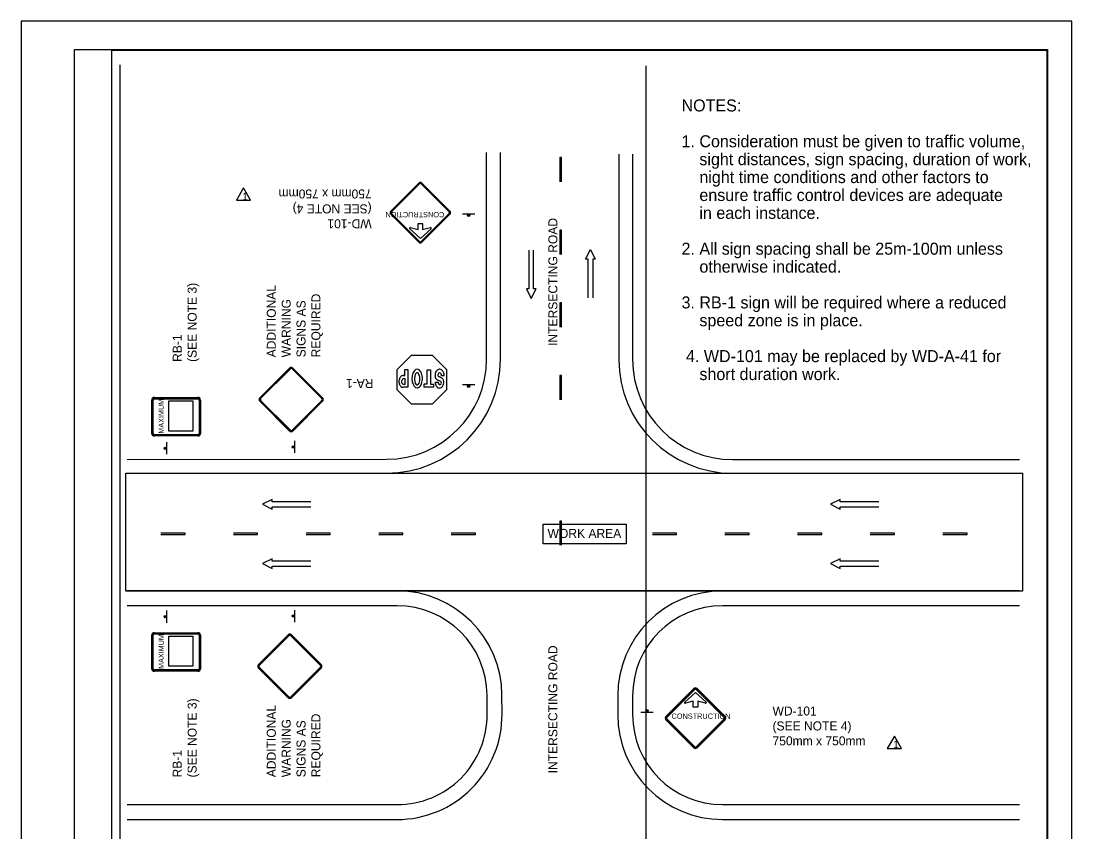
# Model space of a CAD drawing. Extents: x 1373 to 1583, y 130 to 399.
# Drawn here: x 1373.1 to 1583.1, y 237.1 to 399 of the extents above; entities that cross this region are included whole.
import ezdxf

# ---------------------------------------------------------------- set-up
doc = ezdxf.new("R2010")
doc.units = 0
for name, color, linetype in [('Level 1', 7, 'Continuous'), ('Level 10', 7, 'Continuous'), ('Level 17', 7, 'Continuous'), ('Level 18', 7, 'Continuous'), ('Level 2', 7, 'Continuous'), ('Level 60', 7, 'Continuous')]:
    doc.layers.add(name, color=color, linetype=linetype)

msp = doc.modelspace()

# ---------------------------------------------------------------- linework, layer by layer
at = {"layer": 'Level 10'}
for p, q in [((1392.81, 390.25), (1392.81, 138.3)), ((1497.88, 390.01), (1497.88, 138.3)), ((1466.08, 331.48), (1466.08, 372.74)), ((1468.86, 331.48), (1468.86, 372.74)), ((1492.53, 372.39), (1492.53, 331.41)), ((1495.25, 372.39), (1495.25, 331.41)), ((1474.51, 353.24), (1474.51, 345.5)), ((1475.48, 345.5), (1475.48, 353.24)), ((1485.87, 351.43), (1486.84, 353.37)), ((1486.84, 353.37), (1487.8, 351.43)), ((1486.35, 351.43), (1485.87, 351.43)), ((1486.35, 343.69), (1486.35, 351.43)), ((1487.8, 351.43), (1487.32, 351.43)), ((1487.32, 351.43), (1487.32, 343.69)), ((1474.03, 345.5), (1475, 343.56)), ((1474.51, 345.5), (1474.03, 345.5)), ((1475, 343.56), (1475.96, 345.5)), ((1475.96, 345.5), (1475.48, 345.5)), ((1449.75, 328.2), (1449.37, 328.2)), ((1449.39, 328.19), (1449.75, 328.2)), ((1449.75, 328.2), (1449.75, 329.43)), ((1449.75, 329.43), (1450.35, 329.43)), ((1450.35, 329.43), (1450.35, 325.84)), ((1454.23, 329.32), (1454.85, 329.32)), ((1454.23, 326.51), (1454.23, 329.32)), ((1454.85, 329.32), (1454.85, 326.5)), ((1457.63, 328.16), (1457.07, 328.16)), ((1457.45, 328.87), (1457.45, 328.87)), ((1450.35, 325.84), (1449.34, 325.84)), ((1449.43, 326.48), (1449.82, 326.48)), ((1449.43, 326.48), (1449.82, 326.48)), ((1449.82, 327.53), (1449.44, 327.53)), ((1449.82, 327.53), (1449.44, 327.53)), ((1449.82, 326.48), (1449.82, 327.53)), ((1449.82, 326.48), (1449.82, 327.53)), ((1452.25, 325.71), (1452.24, 325.71)), ((1452.28, 326.32), (1452.25, 326.32)), ((1453.6, 325.87), (1453.6, 326.51)), ((1453.6, 326.51), (1454.23, 326.51)), ((1455.51, 325.87), (1453.6, 325.87)), ((1454.85, 326.5), (1455.51, 326.5)), ((1455.51, 326.5), (1455.51, 325.87)), ((1455.81, 326.87), (1456.42, 326.87)), ((1394.25, 311.41), (1446.1, 311.48)), ((1515.25, 311.41), (1572.59, 311.41)), ((1394.25, 308.63), (1446.11, 308.7)), ((1515.25, 308.68), (1572.59, 308.68)), ((1423.23, 303.45), (1421.29, 302.49)), ((1421.29, 302.49), (1423.23, 301.52)), ((1423.23, 302.97), (1423.23, 303.45)), ((1430.97, 302.97), (1423.23, 302.97)), ((1536.75, 303.45), (1534.81, 302.49)), ((1534.81, 302.49), (1536.75, 301.52)), ((1536.75, 302.97), (1536.75, 303.45)), ((1544.49, 302.97), (1536.75, 302.97)), ((1423.23, 301.52), (1423.23, 302)), ((1423.23, 302), (1430.97, 302)), ((1536.75, 301.52), (1536.75, 302)), ((1536.75, 302), (1544.49, 302)), ((1423.23, 291.62), (1421.29, 290.65)), ((1421.29, 290.65), (1423.23, 289.68)), ((1423.23, 291.13), (1423.23, 291.62)), ((1430.97, 291.13), (1423.23, 291.13)), ((1423.23, 289.68), (1423.23, 290.16)), ((1423.23, 290.16), (1430.97, 290.16)), ((1536.75, 291.62), (1534.81, 290.65)), ((1534.81, 290.65), (1536.75, 289.68)), ((1536.75, 291.13), (1536.75, 291.62)), ((1544.49, 291.13), (1536.75, 291.13)), ((1536.75, 289.68), (1536.75, 290.16)), ((1536.75, 290.16), (1544.49, 290.16)), ((1572.59, 285.2), (1394.25, 285.2)), ((1448.19, 285.2), (1394.25, 285.2)), ((1572.59, 285.2), (1513.25, 285.2)), ((1448.19, 282.23), (1394.25, 282.23)), ((1572.59, 282.23), (1513.25, 282.23)), ((1466.21, 260.63), (1466.19, 264.35)), ((1469.17, 260.65), (1469.15, 264.36)), ((1492.29, 264.23), (1492.29, 260.52)), ((1495.25, 264.23), (1495.25, 260.52)), ((1394.25, 242.52), (1448.21, 242.52)), ((1513.25, 242.52), (1572.59, 242.52)), ((1394.25, 239.56), (1448.21, 239.56)), ((1513.25, 239.56), (1572.59, 239.56))]:
    msp.add_line(p, q, dxfattribs=at)
for points in [[(1448.24, 329.4), (1451.1, 332.27), (1455.18, 332.27), (1458.05, 329.4), (1458.05, 325.32), (1455.18, 322.45), (1451.1, 322.45), (1448.24, 325.32)], [(1573.19, 308.68), (1573.19, 285.11), (1394.01, 285.11), (1394.01, 308.68)], [(1477.39, 298.55), (1493.95, 298.55), (1493.95, 294.58), (1477.39, 294.58)]]:
    msp.add_lwpolyline(points, close=True, dxfattribs=at)
for centre, radius, start, end in [((1446.08, 331.48), 20, 270.0814, 0), ((1446.08, 331.48), 22.78, 270.0814, 0), ((1515.25, 331.41), 22.73, 180, 270), ((1515.25, 331.41), 20, 180, 270), ((1450.55, 326.91), 1.98, 158.3153, 168.6699), ((1449.61, 327.29), 0.968, 138.2922, 158.6031), ((1449.61, 327.29), 0.968, 138.2922, 158.6031), ((1449.35, 327.57), 0.597, 115.3838, 142.6188), ((1449.53, 327.34), 0.882, 106.602, 119.8091), ((1449.35, 327.99), 0.207, 79.7909, 113.5419), ((1457.94, 328.25), 2.16, 171.247, 183.9864), ((1457.3, 328.25), 1.53, 185.9097, 201.9865), ((1457.43, 328.1), 1.7, 145.5092, 163.2894), ((1454.04, 325.89), 2.57, 39.479, 43.426), ((1456.83, 328.5), 0.977, 113.1413, 144.9906), ((1456.75, 328.28), 0.399, 172.5761, 210.4776), ((1456.87, 328.33), 0.516, 146.253, 178.7323), ((1456.77, 328.33), 0.435, 214.2083, 254.1552), ((1456.71, 328.33), 0.388, 95.4374, 134.0626), ((1456.69, 328.83), 0.612, 52.0536, 112.7397), ((1454.16, 321.47), 6.9, 64.4624, 68.8312), ((1456.68, 328.29), 0.419, 50.6966, 91.4573), ((1456.62, 328.33), 0.43, 6.8728, 42.7449), ((1456.21, 328.17), 0.856, 359.0172, 13.5172), ((1456.27, 328.24), 1.34, 28.4154, 53.6553), ((1456.6, 326.91), 0.952, 20.4481, 55.1107), ((1455.75, 328.08), 1.88, 2.3841, 24.9519), ((1450.1, 327.03), 1.52, 169.7521, 182.7916), ((1450.1, 327.03), 1.52, 169.7521, 182.7916), ((1450.47, 327.06), 1.89, 183.3903, 195.6597), ((1449.59, 326.78), 0.972, 193.0674, 213.762), ((1449.58, 326.69), 0.915, 209.2241, 228.5308), ((1449.58, 326.69), 0.915, 209.2241, 228.5308), ((1449.39, 326.43), 0.596, 224.8528, 265.0441), ((1449.68, 327), 0.585, 170.3417, 195.2342), ((1449.68, 327), 0.585, 170.3417, 195.2342), ((1449.62, 327.07), 0.522, 146.5086, 177.0313), ((1449.62, 327.07), 0.522, 146.5086, 177.0313), ((1449.66, 326.93), 0.55, 188.6031, 214.217), ((1449.66, 326.93), 0.55, 188.6031, 214.217), ((1449.52, 327.13), 0.406, 101.9191, 145.7868), ((1449.52, 327.13), 0.406, 101.9191, 145.7868), ((1449.49, 326.82), 0.354, 215.1198, 259.3117), ((1449.49, 326.82), 0.354, 215.1198, 259.3117), ((1457.36, 326.9), 1.55, 180.6952, 197.1452), ((1456.97, 326.72), 1.12, 194.564, 229.0063), ((1457.04, 328.58), 1.47, 226.2465, 247.9263), ((1456.69, 326.36), 0.665, 226.1369, 301.3987), ((1456.91, 326.8), 0.506, 170.4412, 219.3244), ((1455.8, 325.23), 2.1, 57.9816, 70.979), ((1456.75, 326.74), 0.346, 227.3017, 289.0119), ((1456.72, 326.71), 0.331, 293.8064, 352.2407), ((1456.76, 326.76), 0.302, 344.131, 58.1476), ((1456.44, 326.7), 1.09, 303.3662, 335.6734), ((1456.02, 326.83), 1.52, 337.7332, 357.1392), ((1456.21, 326.87), 1.34, 354.8171, 15.9183), ((1448.19, 264.23), 20.97, 0.3535, 90), ((1513.25, 264.23), 20.97, 90, 180), ((1448.19, 264.23), 18, 0.3535, 90), ((1513.25, 264.23), 18, 90, 180), ((1448.21, 260.52), 20.97, 270, 0.3535), ((1448.21, 260.52), 18, 270, 0.3535), ((1513.25, 260.52), 20.97, 180, 270), ((1513.25, 260.52), 18, 180, 270)]:
    msp.add_arc(centre, radius, start, end, dxfattribs=at)
for centre, major_axis, ratio, start_param, end_param in [((1452.22, 327.58), (0.01, 1.87), 0.558644, 0.656861, 3.168126), ((1452.22, 327.58), (0.01, 1.87), 0.558644, 4.129576, 6.939747), ((1452.22, 327.54), (-0.01, 1.22), 0.432619, 0.881967, 3.190734), ((1452.22, 327.54), (-0.01, 1.22), 0.432619, 3.890436, 7.165085), ((1452.22, 327.58), (0.01, 1.87), 0.558644, 3.185857, 4.129398), ((1452.22, 327.54), (-0.01, 1.22), 0.432619, 3.239639, 3.888884)]:
    msp.add_ellipse(centre, major_axis=major_axis, ratio=ratio, start_param=start_param, end_param=end_param, dxfattribs=at)
at = {"layer": 'Level 17'}
for p, q in [((1383.77, 393.31), (1383.77, 393.31)), ((1446.94, 361.03), (1452.54, 366.63)), ((1447.03, 360.94), (1452.63, 366.54)), ((1447.11, 360.86), (1452.71, 366.46)), ((1453.01, 366.46), (1458.61, 360.86)), ((1453.09, 366.54), (1458.69, 360.94)), ((1453.17, 366.63), (1458.77, 361.03)), ((1452.54, 354.8), (1446.94, 360.39)), ((1452.63, 354.88), (1447.03, 360.48)), ((1452.71, 354.96), (1447.11, 360.56)), ((1458.61, 360.56), (1453.01, 354.96)), ((1458.69, 360.48), (1453.09, 354.88)), ((1458.77, 360.39), (1453.17, 354.8)), ((1459.09, 360.71), (1459.09, 360.71)), ((1463.71, 360.44), (1461.29, 360.44)), ((1454.88, 357.74), (1454.88, 357.74)), ((1454.88, 357.74), (1454.88, 357.74)), ((1454.88, 357.74), (1454.88, 357.74)), ((1420.77, 323.75), (1426.69, 329.68)), ((1420.86, 323.67), (1426.78, 329.59)), ((1420.94, 323.58), (1426.87, 329.5)), ((1427.22, 329.5), (1433.14, 323.58)), ((1427.31, 329.59), (1433.23, 323.67)), ((1427.39, 329.68), (1433.32, 323.75)), ((1463.71, 326.34), (1461.29, 326.34)), ((1399.7, 323.83), (1408.4, 323.83)), ((1399.7, 323.7), (1408.4, 323.7)), ((1399.7, 323.57), (1408.4, 323.57)), ((1420.77, 323.75), (1420.77, 323.75)), ((1420.85, 323.67), (1420.86, 323.67)), ((1420.94, 323.58), (1420.94, 323.58)), ((1399.19, 316.64), (1399.19, 323.31)), ((1399.32, 316.64), (1399.32, 323.31)), ((1399.45, 316.64), (1399.45, 323.31)), ((1408.66, 323.31), (1408.66, 316.64)), ((1408.79, 323.31), (1408.79, 316.64)), ((1408.91, 323.31), (1408.91, 316.64)), ((1426.69, 317.12), (1420.77, 323.05)), ((1426.78, 317.21), (1420.85, 323.14)), ((1426.87, 317.3), (1420.94, 323.23)), ((1433.14, 323.23), (1427.22, 317.3)), ((1433.23, 323.14), (1427.31, 317.21)), ((1433.32, 323.05), (1427.39, 317.12)), ((1399.19, 316.64), (1399.19, 316.64)), ((1399.24, 316.52), (1399.24, 316.52)), ((1399.29, 316.41), (1399.29, 316.41)), ((1408.4, 316.38), (1399.7, 316.38)), ((1408.4, 316.25), (1399.7, 316.25)), ((1408.4, 316.13), (1399.7, 316.13)), ((1427.74, 312.73), (1427.74, 315.15)), ((1402.16, 312.47), (1402.16, 314.88)), ((1402.16, 278.85), (1402.16, 281.27)), ((1427.74, 278.94), (1427.74, 281.36)), ((1399.19, 269.66), (1399.19, 276.33)), ((1399.32, 269.66), (1399.32, 276.33)), ((1399.45, 269.66), (1399.45, 276.33)), ((1399.7, 276.85), (1408.4, 276.85)), ((1399.7, 276.72), (1408.4, 276.72)), ((1399.7, 276.59), (1408.4, 276.59)), ((1408.66, 276.33), (1408.66, 269.66)), ((1408.79, 276.33), (1408.79, 269.66)), ((1408.91, 276.33), (1408.91, 269.66)), ((1420.5, 270.5), (1426.42, 276.42)), ((1420.58, 270.41), (1426.51, 276.33)), ((1420.67, 270.32), (1426.6, 276.24)), ((1426.94, 276.24), (1432.87, 270.32)), ((1427.03, 276.33), (1432.96, 270.41)), ((1427.12, 276.42), (1433.05, 270.5)), ((1399.19, 269.66), (1399.19, 269.66)), ((1399.24, 269.55), (1399.24, 269.55)), ((1399.29, 269.43), (1399.29, 269.43)), ((1408.4, 269.41), (1399.7, 269.41)), ((1408.4, 269.28), (1399.7, 269.28)), ((1408.4, 269.15), (1399.7, 269.15)), ((1420.49, 270.49), (1420.5, 270.5)), ((1426.42, 263.86), (1420.5, 269.8)), ((1420.58, 270.41), (1420.58, 270.41)), ((1426.51, 263.95), (1420.58, 269.88)), ((1420.67, 270.32), (1420.67, 270.32)), ((1426.6, 264.04), (1420.67, 269.97)), ((1432.87, 269.97), (1426.94, 264.04)), ((1432.96, 269.88), (1427.03, 263.95)), ((1433.05, 269.8), (1427.12, 263.86)), ((1501.91, 260.11), (1507.51, 265.71)), ((1501.99, 260.02), (1507.59, 265.62)), ((1502.08, 259.94), (1507.68, 265.54)), ((1507.97, 265.54), (1513.58, 259.94)), ((1508.06, 265.62), (1513.66, 260.02)), ((1508.14, 265.71), (1513.74, 260.11)), ((1505.81, 262.77), (1505.81, 262.77)), ((1505.81, 262.77), (1505.81, 262.77)), ((1505.81, 262.77), (1505.81, 262.77)), ((1496.93, 261.01), (1499.35, 261.01)), ((1501.59, 259.79), (1501.59, 259.79)), ((1507.51, 253.88), (1501.91, 259.48)), ((1507.59, 253.96), (1501.99, 259.56)), ((1507.68, 254.04), (1502.08, 259.64)), ((1513.58, 259.64), (1507.97, 254.04)), ((1513.66, 259.56), (1508.06, 253.96)), ((1513.74, 259.48), (1508.14, 253.88))]:
    msp.add_line(p, q, dxfattribs=at)
for points in [[(1455, 357.51), (1452.86, 355.56), (1450.72, 357.51)], [(1455, 357.51), (1452.86, 355.56), (1450.72, 357.51)], [(1455, 357.51), (1452.86, 355.56), (1450.72, 357.51)], [(1450.84, 357.74), (1452.42, 357.33), (1452.42, 358.56), (1453.31, 358.56), (1453.31, 357.33), (1454.88, 357.74)], [(1450.84, 357.74), (1452.42, 357.33), (1452.42, 358.56), (1453.31, 358.56), (1453.31, 357.33), (1454.88, 357.74)], [(1450.84, 357.74), (1452.42, 357.33), (1452.42, 358.56), (1453.31, 358.56), (1453.31, 357.33), (1454.88, 357.74)], [(1505.68, 263), (1507.82, 264.94), (1509.97, 263)], [(1505.68, 263), (1507.82, 264.94), (1509.97, 263)], [(1505.68, 263), (1507.82, 264.94), (1509.97, 263)], [(1509.84, 262.77), (1508.27, 263.17), (1508.27, 261.95), (1507.38, 261.95), (1507.38, 263.17), (1505.81, 262.77)], [(1509.84, 262.77), (1508.27, 263.17), (1508.27, 261.95), (1507.38, 261.95), (1507.38, 263.17), (1505.81, 262.77)], [(1509.84, 262.77), (1508.27, 263.17), (1508.27, 261.95), (1507.38, 261.95), (1507.38, 263.17), (1505.81, 262.77)]]:
    msp.add_lwpolyline(points, dxfattribs=at)
for points in [[(1402.58, 323.13), (1407.39, 323.13), (1407.39, 317.11), (1402.58, 317.11)], [(1402.58, 276.15), (1407.39, 276.15), (1407.39, 270.14), (1402.58, 270.14)]]:
    msp.add_lwpolyline(points, close=True, dxfattribs=at)
for centre, radius in [((1462.5, 360.17), 0.242), ((1462.5, 360.17), 0.121), ((1462.5, 326.07), 0.242), ((1462.5, 326.07), 0.121), ((1401.89, 313.68), 0.242), ((1401.89, 313.68), 0.121), ((1427.47, 313.94), 0.242), ((1427.47, 313.94), 0.121), ((1401.89, 280.06), 0.242), ((1401.89, 280.06), 0.121), ((1427.47, 280.16), 0.242), ((1427.47, 280.16), 0.121), ((1498.15, 261.28), 0.242), ((1498.15, 261.28), 0.121)]:
    msp.add_circle(centre, radius, dxfattribs=at)
for centre, radius, start, end in [((1452.86, 366.31), 0.447, 45, 135), ((1452.86, 366.31), 0.329, 45, 135), ((1452.86, 366.31), 0.212, 45, 135), ((1447.26, 360.71), 0.447, 135, 225), ((1447.26, 360.71), 0.329, 135, 225), ((1447.26, 360.71), 0.212, 135, 225), ((1458.46, 360.71), 0.212, 315, 45), ((1458.46, 360.71), 0.329, 315, 45), ((1458.46, 360.71), 0.447, 315, 45), ((1450.81, 357.61), 0.134, 75.5925, 227.6952), ((1450.81, 357.61), 0.134, 75.5925, 227.6952), ((1450.81, 357.61), 0.134, 75.5925, 227.6952), ((1454.91, 357.61), 0.134, 312.3048, 104.4075), ((1454.91, 357.61), 0.134, 312.3048, 104.4075), ((1454.91, 357.61), 0.134, 312.3048, 104.4075), ((1452.86, 355.11), 0.212, 225, 315), ((1452.86, 355.11), 0.447, 225, 315), ((1452.86, 355.11), 0.329, 225, 315), ((1427.04, 329.33), 0.496, 45, 135), ((1427.04, 329.33), 0.371, 45, 135), ((1427.04, 329.33), 0.246, 45, 135), ((1399.7, 323.31), 0.515, 90, 180), ((1399.7, 323.31), 0.386, 90, 180), ((1399.7, 323.31), 0.258, 90, 180), ((1408.4, 323.31), 0.515, 0, 90), ((1408.4, 323.31), 0.386, 0, 90), ((1408.4, 323.31), 0.258, 0, 90), ((1421.12, 323.4), 0.496, 135, 225), ((1421.12, 323.4), 0.371, 135, 225), ((1421.12, 323.4), 0.246, 135, 225), ((1432.97, 323.4), 0.246, 315, 45), ((1432.97, 323.4), 0.371, 315, 45), ((1432.97, 323.4), 0.496, 315, 45), ((1427.04, 317.48), 0.496, 225, 315), ((1427.04, 317.48), 0.371, 225, 315), ((1427.04, 317.48), 0.246, 225, 315), ((1399.7, 316.64), 0.515, 180, 270), ((1399.7, 316.64), 0.386, 180, 270), ((1399.7, 316.64), 0.258, 180, 270), ((1408.4, 316.64), 0.515, 270, 0), ((1408.4, 316.64), 0.386, 270, 0), ((1408.4, 316.64), 0.258, 270, 0), ((1399.7, 276.33), 0.515, 90, 180), ((1399.7, 276.33), 0.386, 90, 180), ((1399.7, 276.33), 0.258, 90, 180), ((1408.4, 276.33), 0.515, 0, 90), ((1408.4, 276.33), 0.386, 0, 90), ((1408.4, 276.33), 0.258, 0, 90), ((1426.77, 276.07), 0.496, 45, 135), ((1426.77, 276.07), 0.371, 45, 135), ((1426.77, 276.07), 0.246, 45, 135), ((1399.7, 269.66), 0.515, 180, 270), ((1399.7, 269.66), 0.386, 180, 270), ((1399.7, 269.66), 0.258, 180, 270), ((1408.4, 269.66), 0.515, 270, 0), ((1408.4, 269.66), 0.386, 270, 0), ((1408.4, 269.66), 0.258, 270, 0), ((1420.84, 270.14), 0.496, 135, 225), ((1420.84, 270.14), 0.371, 135, 225), ((1420.84, 270.14), 0.246, 135, 225), ((1432.7, 270.14), 0.246, 315, 45), ((1432.7, 270.14), 0.371, 315, 45), ((1432.7, 270.14), 0.496, 315, 45), ((1507.82, 265.39), 0.447, 45, 135), ((1507.82, 265.39), 0.329, 45, 135), ((1507.82, 265.39), 0.212, 45, 135), ((1426.77, 264.22), 0.496, 225, 315), ((1426.77, 264.22), 0.371, 225, 315), ((1426.77, 264.22), 0.246, 225, 315), ((1505.77, 262.9), 0.134, 132.3048, 284.4075), ((1505.77, 262.9), 0.134, 132.3048, 284.4075), ((1505.77, 262.9), 0.134, 132.3048, 284.4075), ((1509.87, 262.9), 0.134, 255.5925, 47.6952), ((1509.87, 262.9), 0.134, 255.5925, 47.6952), ((1509.87, 262.9), 0.134, 255.5925, 47.6952), ((1502.22, 259.79), 0.447, 135, 225), ((1502.22, 259.79), 0.329, 135, 225), ((1502.22, 259.79), 0.212, 135, 225), ((1513.42, 259.79), 0.212, 315, 45), ((1513.42, 259.79), 0.329, 315, 45), ((1513.42, 259.79), 0.447, 315, 45), ((1507.82, 254.19), 0.447, 225, 315), ((1507.82, 254.19), 0.329, 225, 315), ((1507.82, 254.19), 0.212, 225, 315)]:
    msp.add_arc(centre, radius, start, end, dxfattribs=at)
at = {"layer": 'Level 2'}
for p, q in [((1480.75, 371.71), (1480.75, 366.87)), ((1481.04, 371.71), (1480.75, 371.71)), ((1481.04, 366.87), (1481.04, 371.71)), ((1480.75, 357.19), (1480.75, 352.36)), ((1481.04, 357.19), (1480.75, 357.19)), ((1481.04, 352.36), (1481.04, 357.19)), ((1480.75, 342.68), (1480.75, 337.84)), ((1481.04, 342.68), (1480.75, 342.68)), ((1481.04, 337.84), (1481.04, 342.68)), ((1480.75, 328.17), (1480.75, 323.33)), ((1481.04, 328.17), (1480.75, 328.17)), ((1481.04, 323.33), (1481.04, 328.17)), ((1480.75, 299.14), (1480.75, 294.3)), ((1481.04, 299.14), (1480.75, 299.14)), ((1481.04, 294.3), (1481.04, 299.14)), ((1405.83, 296.73), (1400.99, 296.73)), ((1400.99, 296.44), (1405.83, 296.44)), ((1405.83, 296.44), (1405.83, 296.73)), ((1420.34, 296.73), (1415.5, 296.73)), ((1415.5, 296.44), (1420.34, 296.44)), ((1420.34, 296.44), (1420.34, 296.73)), ((1434.85, 296.73), (1430.02, 296.73)), ((1430.02, 296.44), (1434.85, 296.44)), ((1434.85, 296.44), (1434.85, 296.73)), ((1449.37, 296.73), (1444.53, 296.73)), ((1444.53, 296.44), (1449.37, 296.44)), ((1449.37, 296.44), (1449.37, 296.73)), ((1463.88, 296.73), (1459.04, 296.73)), ((1459.04, 296.44), (1463.88, 296.44)), ((1463.88, 296.44), (1463.88, 296.73)), ((1504.05, 296.73), (1499.21, 296.73)), ((1499.21, 296.44), (1504.05, 296.44)), ((1504.05, 296.44), (1504.05, 296.73)), ((1518.56, 296.73), (1513.72, 296.73)), ((1513.72, 296.44), (1518.56, 296.44)), ((1518.56, 296.44), (1518.56, 296.73)), ((1533.07, 296.73), (1528.24, 296.73)), ((1528.24, 296.44), (1533.07, 296.44)), ((1533.07, 296.44), (1533.07, 296.73)), ((1547.59, 296.73), (1542.75, 296.73)), ((1542.75, 296.44), (1547.59, 296.44)), ((1547.59, 296.44), (1547.59, 296.73)), ((1562.1, 296.73), (1557.26, 296.73)), ((1557.26, 296.44), (1562.1, 296.44)), ((1562.1, 296.44), (1562.1, 296.73))]:
    msp.add_line(p, q, dxfattribs=at)
at = {"layer": 'Level 60'}
for p, q in [((1583.06, 398.98), (1373.06, 398.98)), ((1373.06, 398.98), (1373.06, 129.98)), ((1583.06, 129.98), (1583.06, 398.98))]:
    msp.add_line(p, q, dxfattribs=at)
for points in [[(1383.77, 393.31), (1578.17, 393.31), (1578.17, 135.56), (1383.77, 135.56)], [(1391.18, 393.17), (1578.06, 393.17), (1578.06, 135.79), (1391.18, 135.79)], [(1417.52, 365.66), (1416.1, 363.19), (1418.94, 363.19)], [(1547.58, 256.22), (1546.16, 253.75), (1549, 253.75)]]:
    msp.add_lwpolyline(points, close=True, dxfattribs=at)

# ---------------------------------------------------------------- texts
at = {"layer": 'Level 1'}
for s, p in [('NOTES:', (1505.04, 380.92)), ('1. Consideration must be given to traffic volume,', (1505.04, 373.77)), ('    sight distances, sign spacing, duration of work,', (1505.04, 370.19)), ('    night time conditions and other factors to ', (1505.04, 366.62)), ('    ensure traffic control devices are adequate ', (1505.04, 363.04)), ('    in each instance.', (1505.04, 359.47)), ('2. All sign spacing shall be 25m-100m unless', (1505.04, 352.32)), ('    otherwise indicated.', (1505.04, 348.74)), ('3. RB-1 sign will be required where a reduced ', (1505.04, 341.59)), ('    speed zone is in place.', (1505.04, 338.02)), (' 4. WD-101 may be replaced by WD-A-41 for ', (1505.04, 330.87)), ('    short duration work.', (1505.04, 327.29))]:
    msp.add_text(s, height=2.4, dxfattribs=at).set_placement(p)
at = {"layer": 'Level 10'}
for s, rotation, p in [('INTERSECTING ROAD', 90, (1480.23, 334.11)), ('WORK AREA', 360, (1478.28, 295.77)), ('INTERSECTING ROAD', 90, (1480.23, 248.77))]:
    msp.add_text(s, height=1.8, rotation=rotation, dxfattribs=at).set_placement(p)
at = {"layer": 'Level 17'}
for s, height, rotation, p in [('750mm x 750mm', 1.8, 180, (1443.12, 365.35)), ('(SEE NOTE 4)', 1.8, 180, (1443.12, 362.37)), ('WD-101', 1.8, 180, (1443.12, 359.4)), ('CONSTRUCTION', 1.0575, 180, (1457.64, 360.85)), ('ADDITIONAL ', 1.7999, 90, (1423.97, 331.83)), ('REQUIRED', 1.8, 90, (1432.88, 331.83)), ('WARNING ', 1.8, 90, (1426.94, 331.83)), ('SIGNS AS ', 1.8, 90, (1429.91, 331.83)), ('RA-1', 1.8, 180, (1443.48, 327.49)), ('MAXIMUM', 1.039, 90, (1401.59, 316.6)), ('MAXIMUM', 1.039, 90, (1401.59, 269.62)), ('ADDITIONAL ', 1.7999, 90, (1423.97, 247.99)), ('REQUIRED', 1.8, 90, (1432.88, 247.99)), ('WARNING ', 1.8, 90, (1426.94, 247.99)), ('SIGNS AS ', 1.8, 90, (1429.91, 247.99))]:
    msp.add_text(s, height=height, rotation=rotation, dxfattribs=at).set_placement(p)
for s, height, p in [('CONSTRUCTION', 1.0575, (1503.05, 259.65)), ('WD-101', 1.8, (1523.22, 260.31)), ('(SEE NOTE 4)', 1.8, (1523.22, 257.33)), ('750mm x 750mm', 1.8, (1523.22, 254.36))]:
    msp.add_text(s, height=height, dxfattribs=at).set_placement(p)
at = {"layer": 'Level 18'}
for s, p in [('(SEE NOTE 3)', (1408.15, 330.92)), ('RB-1', (1405.17, 330.92)), ('(SEE NOTE 3)', (1408.15, 247.95)), ('RB-1', (1405.17, 247.95))]:
    msp.add_text(s, height=1.8, rotation=90, dxfattribs=at).set_placement(p)
at = {"layer": 'Level 60'}
for p in [(1417.29, 363.25), (1547.35, 253.81)]:
    msp.add_text('1', height=1.45, rotation=360, dxfattribs=at).set_placement(p)

doc.saveas('drawing.dxf')
